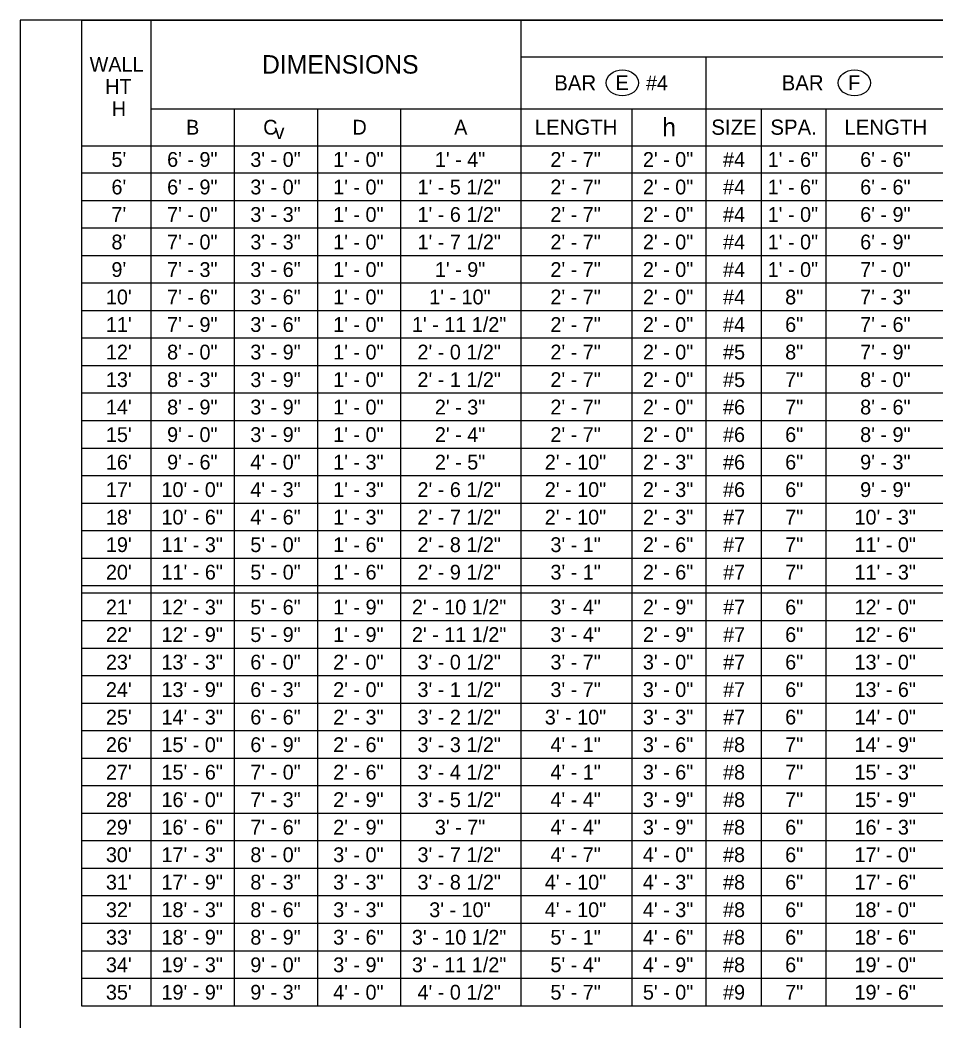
# Model space of a CAD drawing. Extents: x 99862 to 103151, y 100000 to 105076.
# Drawn here: x 99862 to 100853, y 103992 to 105076 of the extents above; entities that cross this region are included whole.
import ezdxf

# ---------------------------------------------------------------- set-up
doc = ezdxf.new("R2010")
doc.units = 0
for name, color, linetype in [('Level 1', 7, 'Continuous'), ('Level 20', 7, 'Continuous'), ('Level 4', 7, 'Continuous')]:
    doc.layers.add(name, color=color, linetype=linetype)

msp = doc.modelspace()

# ---------------------------------------------------------------- linework, layer by layer
at = {"layer": 'Level 1'}
msp.add_lwpolyline([(99862, 102999.5), (103151, 102999.5), (103151, 105075.5), (99862, 105075.5)], close=True, dxfattribs=at)
at = {"layer": 'Level 20'}
for centre in [(100513.5, 105007.5), (100764.5, 105007.5)]:
    msp.add_ellipse(centre, major_axis=(-17.5, 0), ratio=0.8, dxfattribs=at)
at = {"layer": 'Level 4'}
for p, q in [((100004, 104008.6), (100004, 105075.5)), ((100404, 104008.6), (100404, 105075.5)), ((100404, 105035.5), (102554, 105035.5)), ((100604, 104008.6), (100604, 105035.5)), ((100004, 104979.5), (102711, 104979.5)), ((100094, 104008.6), (100094, 104979.5)), ((100184, 104008.6), (100184, 104979.5)), ((100274, 104008.6), (100274, 104979.5)), ((100524, 104008.6), (100524, 104979.5)), ((100664, 104008.6), (100664, 104979.5)), ((100734, 104008.6), (100734, 104979.5)), ((99929, 104939.5), (103151, 104939.5)), ((103151, 104909.7), (99929, 104909.7)), ((103151, 104880), (99929, 104880)), ((103151, 104850.2), (99929, 104850.2)), ((103151, 104820.4), (99929, 104820.4)), ((103151, 104790.6), (99929, 104790.6)), ((103151, 104760.9), (99929, 104760.9)), ((103151, 104731.1), (99929, 104731.1)), ((103151, 104701.3), (99929, 104701.3)), ((103151, 104671.6), (99929, 104671.6)), ((103151, 104641.8), (99929, 104641.8)), ((103151, 104612), (99929, 104612)), ((103151, 104582.2), (99929, 104582.2)), ((103151, 104552.5), (99929, 104552.5)), ((103151, 104522.7), (99929, 104522.7)), ((103151, 104492.9), (99929, 104492.9)), ((103151, 104463.2), (99929, 104463.2)), ((103151, 104455.2), (99929, 104455.2)), ((103151, 104425.4), (99929, 104425.4)), ((103151, 104395.6), (99929, 104395.6)), ((103151, 104365.8), (99929, 104365.8)), ((103151, 104336.1), (99929, 104336.1)), ((103151, 104306.3), (99929, 104306.3)), ((103151, 104276.5), (99929, 104276.5)), ((103151, 104246.8), (99929, 104246.8)), ((103151, 104217), (99929, 104217)), ((103151, 104187.2), (99929, 104187.2)), ((103151, 104157.4), (99929, 104157.4)), ((103151, 104127.7), (99929, 104127.7)), ((103151, 104097.9), (99929, 104097.9)), ((103151, 104068.1), (99929, 104068.1)), ((103151, 104038.4), (99929, 104038.4))]:
    msp.add_line(p, q, dxfattribs=at)
for points in [[(99929, 105075.5), (103151, 105075.5)], [(103151, 104008.6), (99929, 104008.6), (99929, 105075.5)]]:
    msp.add_lwpolyline(points, dxfattribs=at)

# ---------------------------------------------------------------- texts
at = {"layer": 'Level 20'}
for s, height, p in [('WALL', 16, (99937.3, 105019.5)), ('DIMENSIONS', 20, (100123.7, 105017.5)), ('HT', 16, (99954.1, 104995.5)), ('BAR', 16.5, (100439.8, 104999.3)), ('E', 16, (100506.1, 104999.7)), ('#4', 16, (100539, 104999.5)), ('BAR', 16.5, (100685.8, 104999.3)), ('F', 16, (100757.7, 104999.7)), ('H', 16, (99961.2, 104971.5)), ('B', 16, (100041.6, 104951.5)), ('C', 16, (100125, 104951.5)), ('D', 16, (100221.6, 104951.5)), ('A', 16, (100331.6, 104951.5)), ('LENGTH', 16.5, (100418.7, 104951.3)), ('h', 20, (100556.6, 104949.5)), ('SIZE', 16.5, (100609.7, 104951.3)), ('SPA.', 16.5, (100673.6, 104951.3)), ('LENGTH', 16.5, (100753.7, 104951.3)), ('v', 16, (100137.3, 104946.6)), ("5'", 16, (99960.9, 104916.6)), ("6'", 16, (99960.9, 104886.8)), ("7'", 16, (99960.9, 104857.1)), ("8'", 16, (99960.9, 104827.3)), ("9'", 16, (99960.9, 104797.5)), ("10'", 16, (99954.9, 104767.8)), ("11'", 16, (99954.9, 104738)), ("12'", 16, (99954.9, 104708.2)), ("13'", 16, (99954.9, 104678.4)), ("14'", 16, (99954.9, 104648.7)), ("15'", 16, (99954.9, 104618.9)), ("16'", 16, (99954.9, 104589.1)), ("17'", 16, (99954.9, 104559.4)), ("18'", 16, (99954.9, 104529.6)), ("19'", 16, (99954.9, 104499.8)), ("20'", 16, (99954.9, 104470)), ("21'", 16, (99954.9, 104432.3)), ("22'", 16, (99954.9, 104402.5)), ("23'", 16, (99954.9, 104372.7)), ("24'", 16, (99954.9, 104343)), ("25'", 16, (99954.9, 104313.2)), ("26'", 16, (99954.9, 104283.4)), ("27'", 16, (99954.9, 104253.6)), ("28'", 16, (99954.9, 104223.9)), ("29'", 16, (99954.9, 104194.1)), ("30'", 16, (99954.9, 104164.3)), ("31'", 16, (99954.9, 104134.6)), ("32'", 16, (99954.9, 104104.8)), ("33'", 16, (99954.9, 104075)), ("34'", 16, (99954.9, 104045.2)), ("35'", 16, (99954.9, 104015.5))]:
    msp.add_text(s, height=height, dxfattribs=at).set_placement(p)
at = {"layer": 'Level 4'}
for s, p in [('6\' - 9"', (100021.1, 104916.6)), ('3\' - 0"', (100111.1, 104916.6)), ('1\' - 0"', (100200.7, 104916.6)), ('1\' - 4"', (100310.7, 104916.6)), ('2\' - 7"', (100435.7, 104916.6)), ('2\' - 0"', (100535.7, 104916.6)), ('6\' - 9"', (100021.1, 104886.8)), ('3\' - 0"', (100111.1, 104886.8)), ('1\' - 0"', (100200.7, 104886.8)), ('1\' - 5 1/2"', (100291.9, 104886.8)), ('2\' - 7"', (100435.7, 104886.8)), ('2\' - 0"', (100535.7, 104886.8)), ('7\' - 0"', (100021.1, 104857.1)), ('3\' - 3"', (100111.1, 104857.1)), ('1\' - 0"', (100200.7, 104857.1)), ('1\' - 6 1/2"', (100291.9, 104857.1)), ('2\' - 7"', (100435.7, 104857.1)), ('2\' - 0"', (100535.7, 104857.1)), ('7\' - 0"', (100021.1, 104827.3)), ('3\' - 3"', (100111.1, 104827.3)), ('1\' - 0"', (100200.7, 104827.3)), ('1\' - 7 1/2"', (100291.9, 104827.3)), ('2\' - 7"', (100435.7, 104827.3)), ('2\' - 0"', (100535.7, 104827.3)), ('7\' - 3"', (100021.1, 104797.5)), ('3\' - 6"', (100111.1, 104797.5)), ('1\' - 0"', (100200.7, 104797.5)), ('1\' - 9"', (100310.7, 104797.5)), ('2\' - 7"', (100435.7, 104797.5)), ('2\' - 0"', (100535.7, 104797.5)), ('7\' - 6"', (100021.1, 104767.8)), ('3\' - 6"', (100111.1, 104767.8)), ('1\' - 0"', (100200.7, 104767.8)), ('1\' - 10"', (100304.6, 104767.8)), ('2\' - 7"', (100435.7, 104767.8)), ('2\' - 0"', (100535.7, 104767.8)), ('7\' - 9"', (100021.1, 104738)), ('3\' - 6"', (100111.1, 104738)), ('1\' - 0"', (100200.7, 104738)), ('1\' - 11 1/2"', (100285.9, 104738)), ('2\' - 7"', (100435.7, 104738)), ('2\' - 0"', (100535.7, 104738)), ('8\' - 0"', (100021.1, 104708.2)), ('3\' - 9"', (100111.1, 104708.2)), ('1\' - 0"', (100200.7, 104708.2)), ('2\' - 0 1/2"', (100291.9, 104708.2)), ('2\' - 7"', (100435.7, 104708.2)), ('2\' - 0"', (100535.7, 104708.2)), ('8\' - 3"', (100021.1, 104678.4)), ('3\' - 9"', (100111.1, 104678.4)), ('1\' - 0"', (100200.7, 104678.4)), ('2\' - 1 1/2"', (100291.9, 104678.4)), ('2\' - 7"', (100435.7, 104678.4)), ('2\' - 0"', (100535.7, 104678.4)), ('8\' - 9"', (100021.1, 104648.7)), ('3\' - 9"', (100111.1, 104648.7)), ('1\' - 0"', (100200.7, 104648.7)), ('2\' - 3"', (100310.7, 104648.7)), ('2\' - 7"', (100435.7, 104648.7)), ('2\' - 0"', (100535.7, 104648.7)), ('8\' - 6"', (100770.7, 104648.7)), ('9\' - 0"', (100021.1, 104618.9)), ('3\' - 9"', (100111.1, 104618.9)), ('2\' - 4"', (100310.7, 104618.9)), ('2\' - 7"', (100435.7, 104618.9)), ('8\' - 9"', (100770.7, 104618.9)), ('9\' - 6"', (100021.1, 104589.1)), ('4\' - 0"', (100111.1, 104589.1)), ('2\' - 5"', (100310.7, 104589.1)), ('2\' - 10"', (100429.6, 104589.1)), ('9\' - 3"', (100770.7, 104589.1)), ('10\' - 0"', (100015, 104559.4)), ('4\' - 3"', (100111.1, 104559.4)), ('2\' - 6 1/2"', (100291.9, 104559.4)), ('2\' - 10"', (100429.6, 104559.4)), ('9\' - 9"', (100770.7, 104559.4)), ('10\' - 6"', (100015, 104529.6)), ('4\' - 6"', (100111.1, 104529.6)), ('2\' - 7 1/2"', (100291.9, 104529.6)), ('2\' - 10"', (100429.6, 104529.6)), ('10\' - 3"', (100764.6, 104529.6)), ('11\' - 3"', (100015, 104499.8)), ('5\' - 0"', (100111.1, 104499.8)), ('2\' - 8 1/2"', (100291.9, 104499.8)), ('3\' - 1"', (100435.7, 104499.8)), ('11\' - 0"', (100764.6, 104499.8)), ('11\' - 6"', (100015, 104470)), ('5\' - 0"', (100111.1, 104470)), ('2\' - 9 1/2"', (100291.9, 104470)), ('3\' - 1"', (100435.7, 104470)), ('11\' - 3"', (100764.6, 104470)), ('12\' - 3"', (100015, 104432.3)), ('5\' - 6"', (100111.1, 104432.3)), ('2\' - 10 1/2"', (100285.9, 104432.3)), ('3\' - 4"', (100435.7, 104432.3)), ('12\' - 0"', (100764.6, 104432.3)), ('12\' - 9"', (100015, 104402.5)), ('5\' - 9"', (100111.1, 104402.5)), ('2\' - 11 1/2"', (100285.9, 104402.5)), ('3\' - 4"', (100435.7, 104402.5)), ('12\' - 6"', (100764.6, 104402.5)), ('13\' - 3"', (100015, 104372.7)), ('6\' - 0"', (100111.1, 104372.7)), ('3\' - 0 1/2"', (100291.9, 104372.7)), ('3\' - 7"', (100435.7, 104372.7)), ('13\' - 0"', (100764.6, 104372.7)), ('13\' - 9"', (100015, 104343)), ('6\' - 3"', (100111.1, 104343)), ('3\' - 1 1/2"', (100291.9, 104343)), ('3\' - 7"', (100435.7, 104343)), ('13\' - 6"', (100764.6, 104343)), ('14\' - 3"', (100015, 104313.2)), ('6\' - 6"', (100111.1, 104313.2)), ('3\' - 2 1/2"', (100291.9, 104313.2)), ('3\' - 10"', (100429.6, 104313.2)), ('14\' - 0"', (100764.6, 104313.2)), ('15\' - 0"', (100015, 104283.4)), ('6\' - 9"', (100111.1, 104283.4)), ('3\' - 3 1/2"', (100291.9, 104283.4)), ('4\' - 1"', (100435.7, 104283.4)), ('14\' - 9"', (100764.6, 104283.4)), ('15\' - 6"', (100015, 104253.6)), ('7\' - 0"', (100111.1, 104253.6)), ('3\' - 4 1/2"', (100291.9, 104253.6)), ('4\' - 1"', (100435.7, 104253.6)), ('15\' - 3"', (100764.6, 104253.6)), ('16\' - 0"', (100015, 104223.9)), ('7\' - 3"', (100111.1, 104223.9)), ('3\' - 5 1/2"', (100291.9, 104223.9)), ('4\' - 4"', (100435.7, 104223.9)), ('15\' - 9"', (100764.6, 104223.9)), ('16\' - 6"', (100015, 104194.1)), ('7\' - 6"', (100111.1, 104194.1)), ('3\' - 7"', (100310.7, 104194.1)), ('4\' - 4"', (100435.7, 104194.1)), ('16\' - 3"', (100764.6, 104194.1)), ('17\' - 3"', (100015, 104164.3)), ('8\' - 0"', (100111.1, 104164.3)), ('3\' - 7 1/2"', (100291.9, 104164.3)), ('4\' - 7"', (100435.7, 104164.3)), ('17\' - 0"', (100764.6, 104164.3)), ('17\' - 9"', (100015, 104134.6)), ('8\' - 3"', (100111.1, 104134.6)), ('3\' - 8 1/2"', (100291.9, 104134.6)), ('4\' - 10"', (100429.6, 104134.6)), ('17\' - 6"', (100764.6, 104134.6)), ('8\' - 6"', (100111.1, 104104.8)), ('3\' - 10"', (100304.6, 104104.8)), ('4\' - 10"', (100429.6, 104104.8)), ('8\' - 9"', (100111.1, 104075)), ('3\' - 10 1/2"', (100285.9, 104075)), ('5\' - 1"', (100435.7, 104075)), ('9\' - 0"', (100111.1, 104045.2)), ('3\' - 11 1/2"', (100285.9, 104045.2)), ('5\' - 4"', (100435.7, 104045.2)), ('9\' - 3"', (100111.1, 104015.5)), ('4\' - 0 1/2"', (100291.9, 104015.5)), ('5\' - 7"', (100435.7, 104015.5))]:
    msp.add_text(s, height=16, dxfattribs=at).set_placement(p)
for s, p in [('#4', (100622.4, 104916.6)), ('1\' - 6"', (100670.7, 104916.6)), ('6\' - 6"', (100770.7, 104916.6)), ('#4', (100622.4, 104886.8)), ('1\' - 6"', (100670.7, 104886.8)), ('6\' - 6"', (100770.7, 104886.8)), ('#4', (100622.4, 104857.1)), ('1\' - 0"', (100670.7, 104857.1)), ('6\' - 9"', (100770.7, 104857.1)), ('#4', (100622.4, 104827.3)), ('1\' - 0"', (100670.7, 104827.3)), ('6\' - 9"', (100770.7, 104827.3)), ('#4', (100622.4, 104797.5)), ('1\' - 0"', (100670.7, 104797.5)), ('7\' - 0"', (100770.7, 104797.5)), ('#4', (100622.4, 104767.8)), ('8"', (100689.6, 104767.8)), ('7\' - 3"', (100770.7, 104767.8)), ('#4', (100622.4, 104738)), ('6"', (100689.6, 104738)), ('7\' - 6"', (100770.7, 104738)), ('#5', (100622.4, 104708.2)), ('8"', (100689.6, 104708.2)), ('7\' - 9"', (100770.7, 104708.2)), ('#5', (100622.4, 104678.4)), ('7"', (100689.6, 104678.4)), ('8\' - 0"', (100770.7, 104678.4)), ('#6', (100622.4, 104648.7)), ('7"', (100689.6, 104648.7)), ('1\' - 0"', (100200.7, 104618.9)), ('2\' - 0"', (100535.7, 104618.9)), ('#6', (100622.4, 104618.9)), ('6"', (100689.6, 104618.9)), ('1\' - 3"', (100200.7, 104589.1)), ('2\' - 3"', (100535.7, 104589.1)), ('#6', (100622.4, 104589.1)), ('6"', (100689.6, 104589.1)), ('1\' - 3"', (100200.7, 104559.4)), ('2\' - 3"', (100535.7, 104559.4)), ('#6', (100622.4, 104559.4)), ('6"', (100689.6, 104559.4)), ('1\' - 3"', (100200.7, 104529.6)), ('2\' - 3"', (100535.7, 104529.6)), ('#7', (100622.5, 104529.6)), ('7"', (100689.6, 104529.6)), ('1\' - 6"', (100200.7, 104499.8)), ('2\' - 6"', (100535.7, 104499.8)), ('#7', (100622.5, 104499.8)), ('7"', (100689.6, 104499.8)), ('1\' - 6"', (100200.7, 104470)), ('2\' - 6"', (100535.7, 104470)), ('#7', (100622.5, 104470)), ('7"', (100689.6, 104470)), ('1\' - 9"', (100200.7, 104432.3)), ('2\' - 9"', (100535.7, 104432.3)), ('#7', (100622.5, 104432.3)), ('6"', (100689.6, 104432.3)), ('1\' - 9"', (100200.7, 104402.5)), ('2\' - 9"', (100535.7, 104402.5)), ('#7', (100622.5, 104402.5)), ('6"', (100689.6, 104402.5)), ('2\' - 0"', (100200.7, 104372.7)), ('3\' - 0"', (100535.7, 104372.7)), ('#7', (100622.5, 104372.7)), ('6"', (100689.6, 104372.7)), ('2\' - 0"', (100200.7, 104343)), ('3\' - 0"', (100535.7, 104343)), ('#7', (100622.5, 104343)), ('6"', (100689.6, 104343)), ('2\' - 3"', (100200.7, 104313.2)), ('3\' - 3"', (100535.7, 104313.2)), ('#7', (100622.5, 104313.2)), ('6"', (100689.6, 104313.2)), ('2\' - 6"', (100200.7, 104283.4)), ('3\' - 6"', (100535.7, 104283.4)), ('#8', (100622.4, 104283.4)), ('7"', (100689.6, 104283.4)), ('2\' - 6"', (100200.7, 104253.6)), ('3\' - 6"', (100535.7, 104253.6)), ('#8', (100622.4, 104253.6)), ('7"', (100689.6, 104253.6)), ('2\' - 9"', (100200.7, 104223.9)), ('3\' - 9"', (100535.7, 104223.9)), ('#8', (100622.4, 104223.9)), ('7"', (100689.6, 104223.9)), ('2\' - 9"', (100200.7, 104194.1)), ('3\' - 9"', (100535.7, 104194.1)), ('#8', (100622.4, 104194.1)), ('6"', (100689.6, 104194.1)), ('3\' - 0"', (100200.7, 104164.3)), ('4\' - 0"', (100535.7, 104164.3)), ('#8', (100622.4, 104164.3)), ('6"', (100689.6, 104164.3)), ('3\' - 3"', (100200.7, 104134.6)), ('4\' - 3"', (100535.7, 104134.6)), ('#8', (100622.4, 104134.6)), ('6"', (100689.6, 104134.6)), ('18\' - 3"', (100015, 104104.8)), ('3\' - 3"', (100200.7, 104104.8)), ('4\' - 3"', (100535.7, 104104.8)), ('#8', (100622.4, 104104.8)), ('6"', (100689.6, 104104.8)), ('18\' - 0"', (100764.6, 104104.8)), ('18\' - 9"', (100015, 104075)), ('3\' - 6"', (100200.7, 104075)), ('4\' - 6"', (100535.7, 104075)), ('#8', (100622.4, 104075)), ('6"', (100689.6, 104075)), ('18\' - 6"', (100764.6, 104075)), ('19\' - 3"', (100015, 104045.2)), ('3\' - 9"', (100200.7, 104045.2)), ('4\' - 9"', (100535.7, 104045.2)), ('#8', (100622.4, 104045.2)), ('6"', (100689.6, 104045.2)), ('19\' - 0"', (100764.6, 104045.2)), ('19\' - 9"', (100015, 104015.5)), ('4\' - 0"', (100200.7, 104015.5)), ('5\' - 0"', (100535.7, 104015.5)), ('#9', (100622.4, 104015.5)), ('7"', (100689.6, 104015.5)), ('19\' - 6"', (100764.6, 104015.5))]:
    msp.add_text(s, height=16, rotation=360, dxfattribs=at).set_placement(p)

doc.saveas('drawing.dxf')
